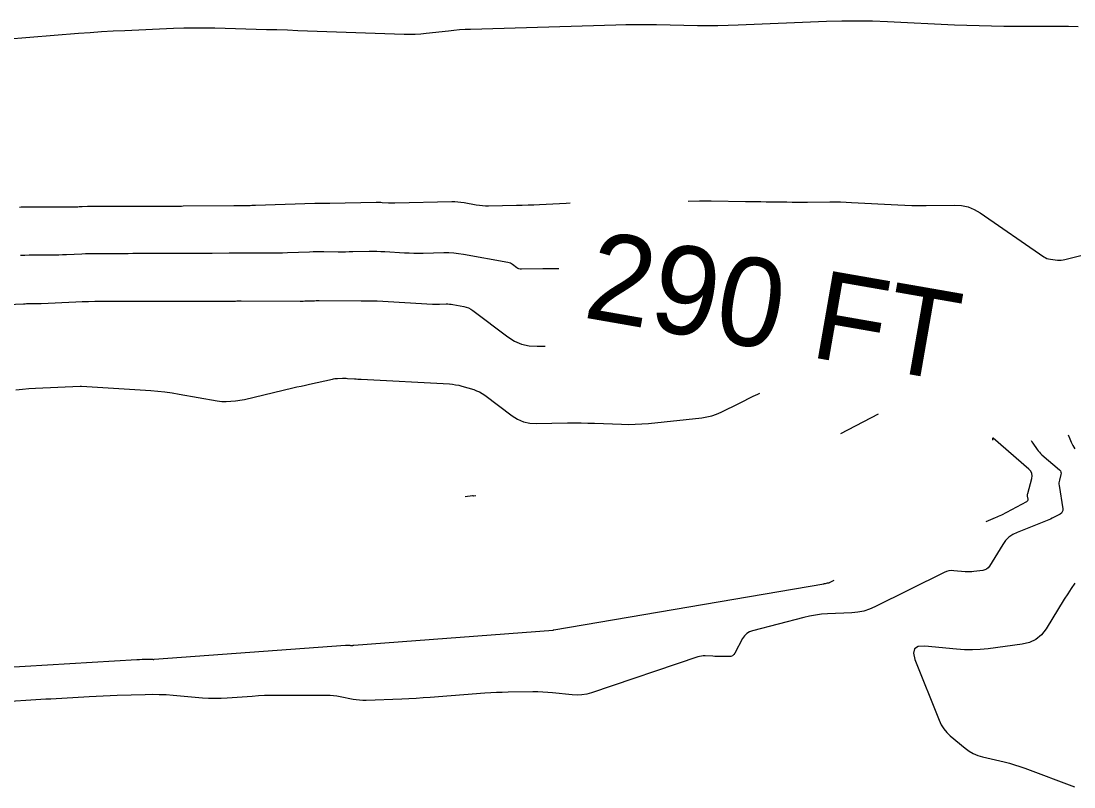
# Model space of a CAD drawing. Extents: x 1768942 to 1774819, y 723037 to 732099.
# Drawn here: x 1769398 to 1769469.5, y 731808.2 to 731860.2 of the extents above; entities that cross this region are included whole.
import ezdxf

# ---------------------------------------------------------------- set-up
doc = ezdxf.new("R2010")
doc.units = 0
doc.layers.add('R_Contour Annot', color=7, linetype='Continuous')
doc.layers.add('R_Contours', color=7, linetype='Continuous')

msp = doc.modelspace()

# ---------------------------------------------------------------- linework, layer by layer
at = {"layer": 'R_Contours'}
for points in [[(1769469.756, 731859.795), (1769469.1, 731859.8), (1769468.443, 731859.803), (1769464.714, 731859.821), (1769463.873, 731859.829), (1769463.033, 731859.847), (1769462.193, 731859.874), (1769461.354, 731859.909), (1769456.819, 731860.126), (1769455.783, 731860.165), (1769454.747, 731860.18), (1769453.711, 731860.172), (1769452.675, 731860.141), (1769446.68, 731859.895), (1769445.988, 731859.872), (1769445.295, 731859.859), (1769444.602, 731859.857), (1769443.909, 731859.865), (1769441.136, 731859.92), (1769440.443, 731859.929), (1769439.75, 731859.93), (1769439.057, 731859.922), (1769438.364, 731859.906), (1769428.513, 731859.615), (1769428.136, 731859.599), (1769427.76, 731859.576), (1769427.384, 731859.544), (1769427.009, 731859.504), (1769425.509, 731859.328), (1769425.134, 731859.291), (1769424.758, 731859.268), (1769424.382, 731859.26), (1769424.005, 731859.267), (1769416.779, 731859.527), (1769416.076, 731859.551), (1769415.373, 731859.574), (1769414.67, 731859.595), (1769413.967, 731859.615), (1769411.156, 731859.691), (1769410.453, 731859.704), (1769409.75, 731859.704), (1769409.047, 731859.692), (1769408.345, 731859.667), (1769405.038, 731859.522), (1769404.253, 731859.484), (1769403.468, 731859.439), (1769402.684, 731859.387), (1769401.9, 731859.328), (1769396.94, 731858.934)], [(1769397.888, 731847.561), (1769398.016, 731847.566), (1769398.144, 731847.57), (1769398.272, 731847.572), (1769398.4, 731847.573), (1769401.767, 731847.585), (1769401.861, 731847.586), (1769401.956, 731847.588), (1769402.05, 731847.591), (1769402.144, 731847.595), (1769402.522, 731847.612), (1769402.616, 731847.615), (1769402.71, 731847.618), (1769402.805, 731847.62), (1769402.899, 731847.621), (1769403.426, 731847.622), (1769403.546, 731847.622), (1769403.665, 731847.622), (1769403.785, 731847.622), (1769403.904, 731847.623), (1769407.615, 731847.631), (1769407.731, 731847.631), (1769407.848, 731847.631), (1769407.964, 731847.632), (1769408.08, 731847.632), (1769408.544, 731847.632), (1769408.66, 731847.632), (1769408.777, 731847.632), (1769408.893, 731847.633), (1769409.009, 731847.635), (1769412.45, 731847.675), (1769412.572, 731847.676), (1769412.694, 731847.677), (1769412.816, 731847.677), (1769412.938, 731847.677), (1769413.427, 731847.677), (1769413.549, 731847.677), (1769413.671, 731847.679), (1769413.793, 731847.681), (1769413.915, 731847.685), (1769417.94, 731847.827), (1769418.024, 731847.829), (1769418.109, 731847.831), (1769418.193, 731847.832), (1769418.278, 731847.831), (1769418.616, 731847.829), (1769418.7, 731847.828), (1769418.785, 731847.828), (1769418.869, 731847.829), (1769418.954, 731847.83), (1769422.094, 731847.885), (1769422.201, 731847.886), (1769422.308, 731847.885), (1769422.415, 731847.882), (1769422.522, 731847.877), (1769422.949, 731847.854), (1769423.056, 731847.849), (1769423.163, 731847.846), (1769423.27, 731847.845), (1769423.377, 731847.847), (1769427.233, 731847.928), (1769427.444, 731847.928), (1769427.653, 731847.916), (1769427.862, 731847.895), (1769428.07, 731847.862), (1769428.9, 731847.712), (1769429.108, 731847.68), (1769429.317, 731847.658), (1769429.526, 731847.646), (1769429.737, 731847.646), (1769431.637, 731847.684), (1769432.024, 731847.693), (1769432.411, 731847.706), (1769432.798, 731847.721), (1769433.185, 731847.739), (1769434.993, 731847.832), (1769435.275, 731847.843)], [(1769443.273, 731847.97), (1769444.046, 731847.977), (1769444.245, 731847.978), (1769444.445, 731847.979), (1769444.644, 731847.978), (1769444.844, 731847.975), (1769447.164, 731847.944), (1769447.516, 731847.939), (1769447.868, 731847.934), (1769448.22, 731847.929), (1769448.571, 731847.925), (1769449.979, 731847.906), (1769450.33, 731847.902), (1769450.682, 731847.9), (1769451.034, 731847.9), (1769451.386, 731847.902), (1769452.893, 731847.914), (1769453.261, 731847.914), (1769453.629, 731847.908), (1769453.998, 731847.897), (1769454.366, 731847.88), (1769457.5, 731847.713), (1769457.981, 731847.691), (1769458.463, 731847.677), (1769458.944, 731847.671), (1769459.426, 731847.673), (1769461.353, 731847.698), (1769461.824, 731847.669), (1769462.274, 731847.57), (1769462.702, 731847.401), (1769463.109, 731847.162), (1769467.413, 731844.191), (1769467.518, 731844.128), (1769467.629, 731844.078), (1769467.744, 731844.043), (1769467.865, 731844.021), (1769468.359, 731843.964), (1769468.482, 731843.955), (1769468.604, 731843.958), (1769468.726, 731843.971), (1769468.846, 731843.996), (1769470.742, 731844.477)], [(1769434.494, 731843.365), (1769434.233, 731843.374), (1769433.962, 731843.378), (1769433.69, 731843.379), (1769433.418, 731843.376), (1769431.964, 731843.346), (1769431.879, 731843.351), (1769431.797, 731843.37), (1769431.72, 731843.402), (1769431.648, 731843.448), (1769431.366, 731843.66), (1769431.294, 731843.708), (1769431.217, 731843.747), (1769431.137, 731843.777), (1769431.052, 731843.797), (1769428.033, 731844.344), (1769427.7, 731844.395), (1769427.365, 731844.43), (1769427.029, 731844.448), (1769426.691, 731844.45), (1769425.291, 731844.42), (1769424.977, 731844.416), (1769424.663, 731844.419), (1769424.349, 731844.427), (1769424.035, 731844.441), (1769422.683, 731844.516), (1769422.418, 731844.528), (1769422.152, 731844.535), (1769421.886, 731844.538), (1769421.621, 731844.536), (1769420.516, 731844.516), (1769420.271, 731844.513), (1769420.026, 731844.511), (1769419.781, 731844.511), (1769419.536, 731844.512), (1769418.556, 731844.52), (1769418.311, 731844.52), (1769418.066, 731844.518), (1769417.821, 731844.514), (1769417.576, 731844.507), (1769416.078, 731844.454), (1769415.747, 731844.444), (1769415.415, 731844.436), (1769415.084, 731844.432), (1769414.752, 731844.431), (1769413.31, 731844.433), (1769413.017, 731844.432), (1769412.724, 731844.431), (1769412.43, 731844.429), (1769412.137, 731844.426), (1769410.964, 731844.413), (1769410.67, 731844.41), (1769410.377, 731844.408), (1769410.084, 731844.406), (1769409.79, 731844.406), (1769408.449, 731844.405), (1769408.132, 731844.405), (1769407.814, 731844.405), (1769407.497, 731844.404), (1769407.179, 731844.404), (1769405.909, 731844.401), (1769405.591, 731844.4), (1769405.274, 731844.399), (1769404.956, 731844.399), (1769404.639, 731844.398), (1769403.163, 731844.395), (1769402.902, 731844.393), (1769402.642, 731844.389), (1769402.382, 731844.381), (1769402.122, 731844.371), (1769401.082, 731844.324), (1769400.822, 731844.314), (1769400.562, 731844.306), (1769400.302, 731844.301), (1769400.042, 731844.299), (1769398.834, 731844.294), (1769398.546, 731844.292), (1769398.259, 731844.286), (1769397.971, 731844.278)], [(1769393.831, 731840.812), (1769398.174, 731841.003), (1769398.273, 731841.007), (1769398.373, 731841.01), (1769398.472, 731841.012), (1769398.572, 731841.013), (1769398.97, 731841.014), (1769399.069, 731841.015), (1769399.169, 731841.017), (1769399.268, 731841.02), (1769399.368, 731841.024), (1769401.723, 731841.13), (1769402.148, 731841.147), (1769402.574, 731841.159), (1769403, 731841.167), (1769403.426, 731841.17), (1769406.658, 731841.176), (1769406.77, 731841.176), (1769406.883, 731841.177), (1769406.995, 731841.177), (1769407.107, 731841.177), (1769407.556, 731841.178), (1769407.668, 731841.178), (1769407.781, 731841.179), (1769407.893, 731841.179), (1769408.005, 731841.179), (1769411.783, 731841.18), (1769411.88, 731841.18), (1769411.977, 731841.18), (1769412.074, 731841.181), (1769412.171, 731841.182), (1769412.559, 731841.187), (1769412.656, 731841.188), (1769412.753, 731841.188), (1769412.85, 731841.189), (1769412.947, 731841.189), (1769416.944, 731841.185), (1769417.052, 731841.185), (1769417.16, 731841.186), (1769417.268, 731841.189), (1769417.376, 731841.192), (1769417.808, 731841.207), (1769417.915, 731841.21), (1769418.023, 731841.212), (1769418.131, 731841.213), (1769418.239, 731841.213), (1769421.085, 731841.19), (1769421.176, 731841.189), (1769421.267, 731841.189), (1769421.358, 731841.19), (1769421.45, 731841.191), (1769421.814, 731841.198), (1769421.905, 731841.199), (1769421.997, 731841.198), (1769422.088, 731841.195), (1769422.179, 731841.191), (1769425.933, 731840.984), (1769426.047, 731840.979), (1769426.162, 731840.976), (1769426.277, 731840.975), (1769426.392, 731840.976), (1769426.851, 731840.986), (1769426.965, 731840.985), (1769427.08, 731840.979), (1769427.193, 731840.967), (1769427.307, 731840.95), (1769428.063, 731840.813), (1769428.223, 731840.774), (1769428.375, 731840.718), (1769428.519, 731840.645), (1769428.656, 731840.554), (1769431.041, 731838.761), (1769431.496, 731838.471), (1769431.979, 731838.268), (1769432.49, 731838.151), (1769433.029, 731838.119), (1769433.581, 731838.13)], [(1769397.646, 731835.163), (1769398.093, 731835.207), (1769398.54, 731835.242), (1769398.988, 731835.268), (1769402.022, 731835.409), (1769402.029, 731835.41), (1769402.036, 731835.41), (1769402.043, 731835.409), (1769402.049, 731835.409), (1769402.083, 731835.405), (1769402.097, 731835.404), (1769402.104, 731835.404), (1769406.8, 731835.106), (1769407.286, 731835.068), (1769407.772, 731835.016), (1769408.255, 731834.951), (1769408.737, 731834.873), (1769411.317, 731834.415), (1769411.47, 731834.392), (1769411.624, 731834.379), (1769411.779, 731834.375), (1769411.933, 731834.381), (1769412.554, 731834.422), (1769412.709, 731834.436), (1769412.862, 731834.456), (1769413.015, 731834.482), (1769413.167, 731834.514), (1769416.446, 731835.287), (1769416.73, 731835.354), (1769417.015, 731835.42), (1769417.301, 731835.484), (1769417.586, 731835.548), (1769419.133, 731835.89), (1769419.217, 731835.907), (1769419.301, 731835.919), (1769419.386, 731835.928), (1769419.471, 731835.932), (1769419.813, 731835.943), (1769419.898, 731835.944), (1769419.983, 731835.944), (1769420.069, 731835.942), (1769420.154, 731835.937), (1769420.644, 731835.907), (1769420.754, 731835.9), (1769420.865, 731835.894), (1769420.975, 731835.888), (1769421.085, 731835.882), (1769427.079, 731835.559), (1769427.29, 731835.541), (1769427.498, 731835.511), (1769427.705, 731835.469), (1769427.91, 731835.415), (1769428.724, 731835.173), (1769428.924, 731835.104), (1769429.114, 731835.019), (1769429.297, 731834.916), (1769429.471, 731834.797), (1769431.328, 731833.401), (1769431.705, 731833.161), (1769432.105, 731832.992), (1769432.529, 731832.895), (1769432.975, 731832.869), (1769435.09, 731832.912), (1769435.549, 731832.917), (1769436.009, 731832.917), (1769436.468, 731832.909), (1769436.928, 731832.895), (1769438.765, 731832.825), (1769439.224, 731832.816), (1769439.682, 731832.823), (1769440.14, 731832.847), (1769440.598, 731832.887), (1769444.209, 731833.272), (1769444.55, 731833.323), (1769444.881, 731833.404), (1769445.205, 731833.513), (1769445.52, 731833.652), (1769446.762, 731834.266), (1769447.073, 731834.419), (1769447.384, 731834.57), (1769447.696, 731834.721), (1769448.008, 731834.871), (1769448.149, 731834.938)], [(1769453.652, 731832.203), (1769456.198, 731833.535)], [(1769463.507, 731826.237), (1769464.145, 731826.491), (1769464.25, 731826.534), (1769464.355, 731826.581), (1769464.457, 731826.63), (1769464.559, 731826.682), (1769466.276, 731827.594), (1769466.314, 731827.62), (1769466.338, 731827.653), (1769466.35, 731827.693), (1769466.349, 731827.739), (1769466.318, 731827.936), (1769466.313, 731827.985), (1769466.313, 731828.034), (1769466.318, 731828.083), (1769466.329, 731828.131), (1769466.599, 731829.153), (1769466.623, 731829.332), (1769466.599, 731829.496), (1769466.527, 731829.644), (1769466.405, 731829.778), (1769463.978, 731831.879), (1769463.965, 731831.887), (1769463.956, 731831.888), (1769463.95, 731831.881), (1769463.947, 731831.866), (1769463.939, 731831.755)], [(1769469.073, 731832.101), (1769469.18, 731831.838), (1769469.283, 731831.605), (1769469.398, 731831.379), (1769469.526, 731831.159)], [(1769466.555, 731831.728), (1769466.608, 731831.637), (1769466.676, 731831.533), (1769466.962, 731831.123), (1769467.037, 731831.023), (1769467.117, 731830.928), (1769467.203, 731830.839), (1769467.294, 731830.754), (1769468.481, 731829.728), (1769468.542, 731829.661), (1769468.578, 731829.586), (1769468.59, 731829.503), (1769468.578, 731829.414), (1769468.479, 731829.039), (1769468.459, 731828.945), (1769468.449, 731828.85), (1769468.449, 731828.755), (1769468.459, 731828.66), (1769468.702, 731827.093), (1769468.704, 731826.979), (1769468.675, 731826.881), (1769468.614, 731826.799), (1769468.521, 731826.733), (1769468.085, 731826.501), (1769467.975, 731826.445), (1769467.864, 731826.392), (1769467.752, 731826.341), (1769467.638, 731826.294), (1769465.609, 731825.488), (1769465.313, 731825.343), (1769465.051, 731825.158), (1769464.823, 731824.932), (1769464.63, 731824.665), (1769463.73, 731823.201), (1769463.642, 731823.086), (1769463.537, 731822.999), (1769463.413, 731822.939), (1769463.272, 731822.906), (1769462.674, 731822.828), (1769462.524, 731822.813), (1769462.374, 731822.806), (1769462.224, 731822.808), (1769462.074, 731822.819), (1769461.323, 731822.892), (1769461.15, 731822.897), (1769460.982, 731822.878), (1769460.818, 731822.835), (1769460.658, 731822.769), (1769455.954, 731820.437), (1769455.579, 731820.275), (1769455.194, 731820.154), (1769454.798, 731820.073), (1769454.392, 731820.034), (1769452.745, 731819.96), (1769452.335, 731819.931), (1769451.928, 731819.881), (1769451.524, 731819.809), (1769451.124, 731819.716), (1769447.644, 731818.816), (1769447.434, 731818.74), (1769447.253, 731818.626), (1769447.1, 731818.476), (1769446.977, 731818.289), (1769446.456, 731817.304), (1769446.381, 731817.196), (1769446.288, 731817.119), (1769446.177, 731817.074), (1769446.047, 731817.059), (1769445.469, 731817.064), (1769445.34, 731817.066), (1769445.211, 731817.069), (1769445.082, 731817.074), (1769444.953, 731817.081), (1769444.437, 731817.112), (1769444.309, 731817.114), (1769444.182, 731817.103), (1769444.058, 731817.08), (1769443.934, 731817.045), (1769436.714, 731814.609), (1769436.394, 731814.52), (1769436.071, 731814.466), (1769435.744, 731814.448), (1769435.413, 731814.465), (1769434.081, 731814.604), (1769433.748, 731814.634), (1769433.414, 731814.655), (1769433.08, 731814.665), (1769432.745, 731814.666), (1769431.055, 731814.645), (1769430.662, 731814.638), (1769430.269, 731814.623), (1769429.877, 731814.603), (1769429.484, 731814.576), (1769425.766, 731814.291), (1769425.288, 731814.257), (1769424.809, 731814.227), (1769424.33, 731814.202), (1769423.851, 731814.181), (1769421.426, 731814.089), (1769421.202, 731814.087), (1769420.978, 731814.099), (1769420.755, 731814.123), (1769420.534, 731814.162), (1769419.651, 731814.342), (1769419.429, 731814.381), (1769419.207, 731814.409), (1769418.983, 731814.426), (1769418.758, 731814.431), (1769415.382, 731814.429), (1769414.959, 731814.425), (1769414.535, 731814.413), (1769414.112, 731814.393), (1769413.69, 731814.366), (1769411.999, 731814.242), (1769411.577, 731814.219), (1769411.155, 731814.213), (1769410.732, 731814.224), (1769410.31, 731814.252), (1769408.318, 731814.424), (1769407.845, 731814.458), (1769407.371, 731814.478), (1769406.898, 731814.484), (1769406.423, 731814.477), (1769404.52, 731814.418), (1769404.045, 731814.402), (1769403.57, 731814.383), (1769403.095, 731814.36), (1769402.62, 731814.335), (1769400.014, 731814.185), (1769399.674, 731814.165), (1769399.335, 731814.145), (1769398.995, 731814.125), (1769398.655, 731814.105), (1769397.296, 731814.023)], [(1769428.134, 731827.933), (1769428.647, 731827.985), (1769428.656, 731827.986), (1769428.67, 731827.985), (1769428.676, 731827.985), (1769428.681, 731827.983), (1769428.698, 731827.978), (1769428.701, 731827.977), (1769428.705, 731827.977), (1769428.709, 731827.977), (1769428.713, 731827.977), (1769428.87, 731827.993)], [(1769390.679, 731815.952), (1769405.856, 731816.865), (1769405.902, 731816.868), (1769405.947, 731816.87), (1769405.993, 731816.873), (1769406.039, 731816.876), (1769406.231, 731816.887), (1769406.272, 731816.889), (1769406.313, 731816.891), (1769406.354, 731816.893), (1769406.395, 731816.894), (1769406.559, 731816.899), (1769406.6, 731816.9), (1769406.64, 731816.899), (1769406.681, 731816.897), (1769406.722, 731816.895), (1769406.885, 731816.88), (1769406.926, 731816.878), (1769406.967, 731816.877), (1769407.008, 731816.877), (1769407.048, 731816.879), (1769420.023, 731817.833), (1769420.05, 731817.835), (1769420.077, 731817.836), (1769420.104, 731817.837), (1769420.131, 731817.837), (1769420.272, 731817.837), (1769420.283, 731817.837), (1769420.293, 731817.836), (1769420.304, 731817.835), (1769420.314, 731817.833), (1769420.355, 731817.825), (1769420.365, 731817.823), (1769420.375, 731817.822), (1769420.385, 731817.822), (1769420.396, 731817.822), (1769420.508, 731817.826), (1769420.53, 731817.827), (1769420.552, 731817.828), (1769420.574, 731817.829), (1769420.597, 731817.831), (1769434.109, 731818.866), (1769434.12, 731818.867), (1769434.126, 731818.866), (1769434.127, 731818.867), (1769434.15, 731818.874), (1769434.158, 731818.877), (1769434.166, 731818.878), (1769452.483, 731822.007), (1769452.511, 731822.012), (1769452.538, 731822.017), (1769452.565, 731822.023), (1769452.592, 731822.03), (1769452.731, 731822.066), (1769452.743, 731822.069), (1769452.754, 731822.071), (1769452.765, 731822.072), (1769452.777, 731822.073), (1769452.823, 731822.075), (1769452.834, 731822.076), (1769452.845, 731822.078), (1769452.856, 731822.082), (1769452.867, 731822.086), (1769453.193, 731822.248)], [(1769469.53, 731822.038), (1769469.282, 731821.683), (1769469.042, 731821.323), (1769468.811, 731820.957), (1769467.576, 731818.949), (1769467.263, 731818.54), (1769466.888, 731818.228), (1769466.449, 731818.013), (1769465.947, 731817.896), (1769463.644, 731817.598), (1769463.108, 731817.544), (1769462.572, 731817.52), (1769462.035, 731817.527), (1769461.497, 731817.564), (1769459.347, 731817.773), (1769458.902, 731817.756), (1769458.641, 731817.6), (1769458.564, 731817.306), (1769458.671, 731816.874), (1769460.314, 731812.742), (1769460.453, 731812.444), (1769460.625, 731812.171), (1769460.831, 731811.922), (1769461.069, 731811.696), (1769462.089, 731810.842), (1769462.353, 731810.645), (1769462.633, 731810.483), (1769462.931, 731810.356), (1769463.247, 731810.263), (1769464.735, 731809.916), (1769465.089, 731809.828), (1769465.439, 731809.727), (1769465.787, 731809.616), (1769466.13, 731809.493), (1769469.504, 731808.221)]]:
    msp.add_lwpolyline(points, dxfattribs=at)

# ---------------------------------------------------------------- texts
at = {"layer": 'R_Contour Annot'}
msp.add_text('290 FT', height=6, rotation=350.10751, dxfattribs=at).set_placement((1769436.057, 731840.092))

doc.saveas('drawing.dxf')
